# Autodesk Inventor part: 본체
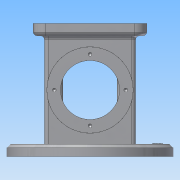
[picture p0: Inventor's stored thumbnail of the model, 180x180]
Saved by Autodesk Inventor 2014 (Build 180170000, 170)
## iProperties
Created: 2019-08
Part Number: 본체
Material: 알루미늄 6061
Document SubType Name: Modeling
Designer: net
Density: 2.71 g/cm^3
Appearance: 알루미늄 - 평지
Mass: 1044.9 g
Surface Area: 795.712 cm^2
Volume: 385.571 cm^3
Author: net
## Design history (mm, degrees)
sketch "스케치1"
  geometry: C1 r 67.5 at (0, 0); 1 further point
  constraints: 1 centre point, 1 coincident
  dimensions: "d0" = 135 diameter of C1
extrude "돌출1" new body sketch "스케치1" distance "d1" = 10; taper "d2" = 0 deg
sketch "스케치2"
  geometry: L1 (-37, 33)-(37, 33); L2 (37, 33)-(37, -33); L3 (37, -33)-(-37, -33); L4 (-37, -33)-(-37, 33); C1 r 67.5 at (0, 0) reference; 2 further points
  constraints: 8 end point, 2 midpoint, 1 horizontal, 1 horizontal alignment, 1 parallel, 1 perpendicular, 1 vertical alignment
  dimensions: "d3" = 74 distance of L1.start L1.end; "d4" = 66 distance of L1.end L2.end; "d5" = 74 distance of L2.end L3.end
extrude "돌출2" join sketch "스케치2" distance "d6" = 98; taper "d7" = 0 deg
sketch "스케치3"
  geometry: L1 (37, 33)-(-37, 33) reference; L2 (-37, 33)-(-37, -33) reference; L3 (-37, -33)-(37, -33) reference; L4 (37, -33)-(37, 33) reference; L5 (-46, 41)-(46, 41); L6 (46, 41)-(46, -41); L7 (46, -41)-(-46, -41); L8 (-46, -41)-(-46, 41); 3 further points
  constraints: 8 end point, 2 midpoint, 2 perpendicular, 1 horizontal alignment, 1 parallel, 1 vertical alignment
  dimensions: "d8" = 92 distance of L5.start L5.end; "d9" = 82 distance of L5.end L6.end; "d10" = 92 distance of L6.end L7.end
extrude "돌출3" join sketch "스케치3" distance "d11" = 10; taper "d12" = 0 deg
sketch "스케치4"
  geometry: C1 r 67.5 at (0, 0) reference; C2 r 4.5 at (0, 59); C3 r 4.5 at (-59, 0); C4 r 4.5 at (0, -59); A1 r 59 centre (0, 0) between (0, 59) and (-59, 0)
  constraints: 4 centre point, 3 point on circle, 1 coincident
  dimensions: "d13" = 118 diameter of A1; "d14" = 9 diameter of C2; "d15" = 9 diameter of C3; "d16" = 9 diameter of C4
extrude "돌출4" cut sketch "스케치4" distance "d17" = 10; taper "d18" = 0 deg
sketch "스케치5"
  geometry: L1 (-30.5, -10)-(104.5, -10) reference; L2 (37, -10)-(37, 44); C1 r 24 at (37, 44); C2 r 35 at (37, 44)
  constraints: 2 centre point, 2 coincident, 2 end point, 1 perpendicular
  dimensions: "d19" = 54 distance of L2.start L2.end; "d20" = 48 diameter of C1; "d21" = 70 diameter of C2
extrude "돌출5" cut sketch "스케치5" distance "d22" = 3; taper "d23" = 0 deg
extrude "돌출6" cut sketch "스케치5" distance "d24" = 11; taper "d25" = 0 deg
sketch "스케치6"
  geometry: C1 r 67.5 at (0, 0) reference; C2 r 25 at (0, 0)
  constraints: 1 centre point, 1 coincident
  dimensions: "d26" = 50 diameter of C2
extrude "돌출7" cut sketch "스케치6" distance "d27" = 18; taper "d28" = 0 deg
sketch "스케치7"
  geometry: L1 (-26, -26)-(26, -26); L2 (26, -26)-(26, 26); L3 (26, 26)-(-26, 26); L4 (-26, 26)-(-26, -26); L5 (-26, -26)-(26, 26); L6 (26, -26)-(-26, 26); 1 further point
  constraints: 12 end point, 2 midpoint, 2 parallel, 1 horizontal, 1 perpendicular
  dimensions: "d29" = 52 distance of L2.end L3.end; "d30" = 52 distance of L1.end L2.end
extrude "돌출8" cut sketch "스케치7" distance "d31" = 8; taper "d32" = 0 deg
sketch "스케치8"
  geometry: L1 (-22, -22)-(22, -22); L2 (22, -22)-(22, 22); L3 (22, 22)-(-22, 22); L4 (-22, 22)-(-22, -22); L5 (-22, -22)-(22, 22); L6 (22, -22)-(-22, 22); 1 further point
  constraints: 12 end point, 2 midpoint, 2 parallel, 1 horizontal, 1 perpendicular
  dimensions: "d33" = 44 distance of L2.end L3.end; "d34" = 44 distance of L1.end L2.end
extrude "돌출9" cut sketch "스케치8" distance "d35" = 74; taper "d36" = 0 deg
sketch "스케치9"
  geometry: C1 r 25 at (0, 0) reference; C2 r 12.5 at (0, 0)
  constraints: 1 centre point, 1 coincident
  dimensions: "d37" = 25 diameter of C2
extrude "돌출10" cut sketch "스케치9" distance "d38" = 74; taper "d39" = 0 deg
sketch "스케치10"
  geometry: C1 r 35 at (0, 0) reference; A1 r 29 centre (0, 0) between (0, 29) and (29, 0); 3 further points
  constraints: 4 point on circle, 1 centre point, 1 coincident
  dimensions: "d40" = 58 diameter of A1
hole "구멍1" sketch "스케치10" at (0, 29), (29, 0), (0, -29), (-29, 0) diameter "d41" = 3.242; stored, may be unused: countersink angle "d45" = 90 deg, drill point angle "d47" = 118 deg; dims "d42" = 4, "d43" = 4, "d44" = 2, "d46" = 6
fillet "모깎기1" dims "d48" = 10
sketch "스케치11"
  geometry: L1 (-36, 41)-(36, 41) reference; L2 (-36, 31)-(36, 31); L3 (36, 31)-(36, -31); A1 r 10 centre (-36, 31) between (-36, 41) and (-46, 31) reference; A2 r 10 centre (-36, -31) between (-46, -31) and (-36, -41) reference; A3 r 10 centre (36, -31) between (36, -41) and (46, -31) reference; A4 r 10 centre (36, 31) between (46, 31) and (36, 41) reference; 5 further points
  constraints: 4 coincident, 4 end point, 1 parallel, 1 perpendicular
hole "구멍2" sketch "스케치11" at (-36, 31), (-36, -31), (36, -31), (36, 31) diameter "d49" = 3.242; stored, may be unused: countersink angle "d53" = 90 deg, drill point angle "d55" = 118 deg; dims "d50" = 4, "d51" = 4, "d52" = 2, "d54" = 6
chamfer "모따기1" distance "d56" = 3; stored, may be unused: second distance "d57" = 2, angle "d58" = 45 deg
fillet "모깎기2" dims "d59" = 3
fillet "모깎기3" dims "d60" = 3
sketch "스케치12"
  geometry: L1 (10, 55)-(10, 5) reference; L2 (10, 30)-(-27, 30); L3 (-27, 30)-(-70, 30); 1 further point
  constraints: 4 end point, 2 coincident, 1 collinear, 1 perpendicular
  dimensions: "d61" = 37 distance of L2.start L2.end; "d62" = 43 distance of L3.start L3.end
hole "구멍3" sketch "스케치12" at (-27, 30), (-70, 30) diameter "d63" = 4.917; stored, may be unused: countersink angle "d67" = 90 deg, drill point angle "d69" = 118 deg; dims "d64" = 4, "d65" = 4, "d66" = 2, "d68" = 20
sketch "스케치14"
  geometry: C1 r 64.5 at (0, 0) reference; C2 r 59 at (0, 0)
  constraints: 1 centre point, 1 coincident, 1 other
  dimensions: "d71" = 118 diameter of C2
feature "엠보싱1" sketch "스케치14" dims "d2" = 0, "d8" = 92, "d9" = 82, "d10" = 92, "d72" = 0.5, "d73" = 0
chamfer "모따기2" distance "d74" = 1; stored, may be unused: second distance "d75" = 2, angle "d76" = 45 deg
fillet "모깎기4" dims "d77" = 3
fillet "모깎기5" dims "d78" = 3
fillet "모깎기6" dims "d79" = 3
node "솔리드1"
mirror "대칭1"
mirror "대칭2"
